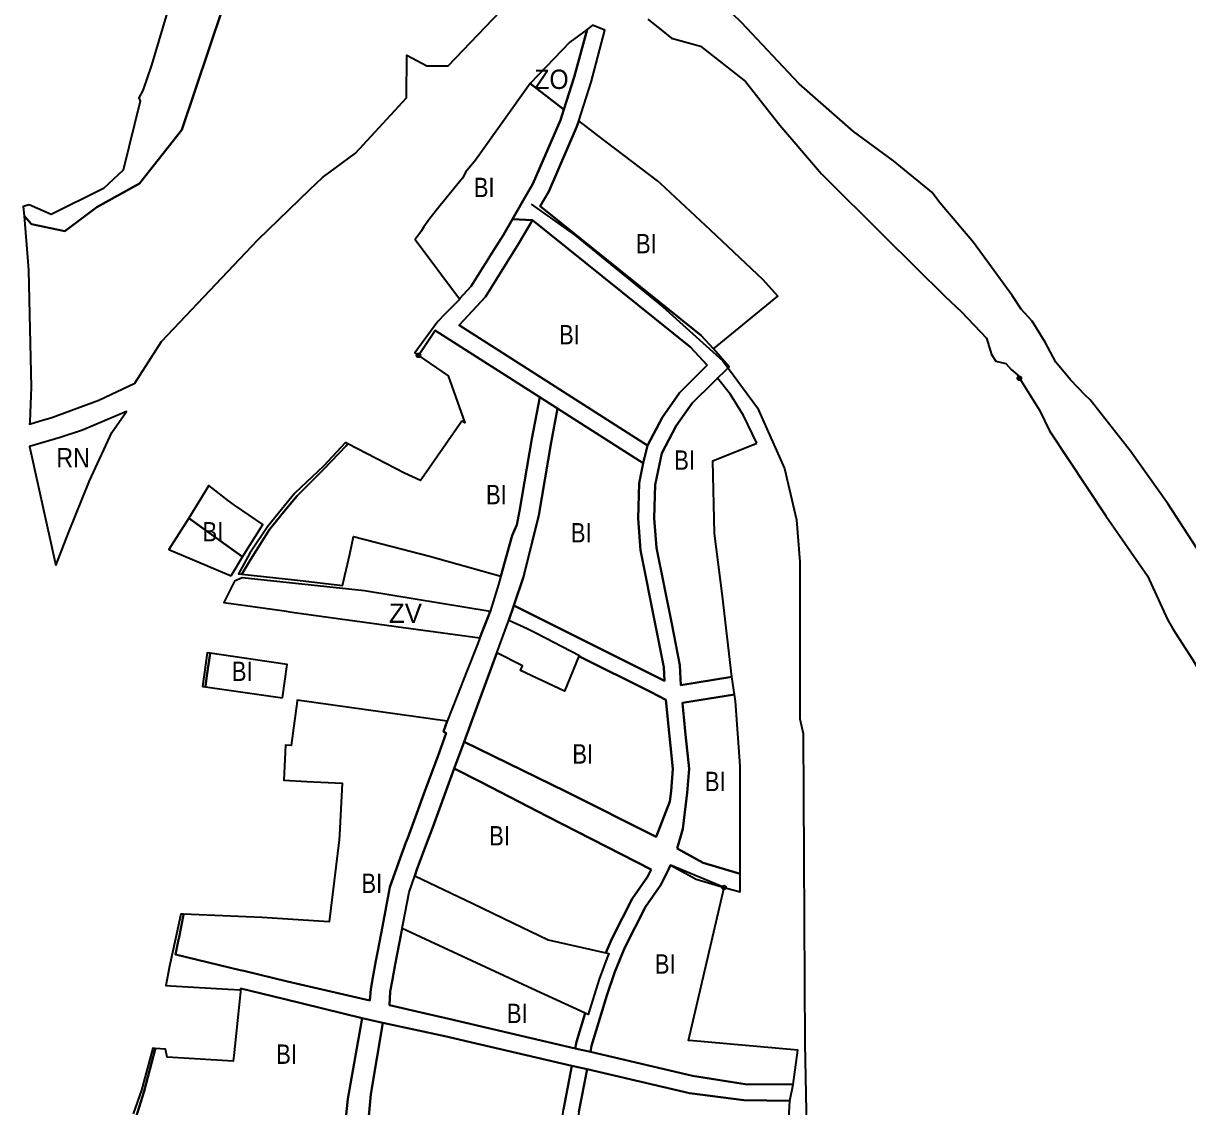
# Model space of a CAD drawing. Extents: x -650276 to -642489, y -1074311 to -1066658.
# Drawn here: x -645939 to -645218, y -1069899 to -1069228 of the extents above; entities that cross this region are included whole.
import ezdxf

# ---------------------------------------------------------------- set-up
doc = ezdxf.new("R2010")
doc.units = 0
doc.header["$LTSCALE"] = 4.8
doc.header["$PDMODE"] = 32
doc.header["$PDSIZE"] = 2.4
for name, color, linetype, lineweight in [('15', 7, 'Continuous', 35), ('2', 7, 'Continuous', 35), ('24', 7, 'Continuous', 35), ('40', 7, 'Continuous', 35), ('42', 7, 'Continuous', 35), ('48', 7, 'Continuous', 35), ('54', 7, 'Continuous', 35), ('7', 7, 'Continuous', 35)]:
    doc.layers.add(name, color=color, linetype=linetype, lineweight=lineweight)
doc.layers.add('62', color=7, linetype='Continuous')

msp = doc.modelspace()

# ---------------------------------------------------------------- linework, layer by layer
at = {"layer": '15'}
for p, q in [((-645552.336, -1069489.579), (-645555.072, -1069500.545)), ((-645638.203, -1069597.8), (-645635.153, -1069588.78))]:
    msp.add_line(p, q, dxfattribs=at)
for points in [[(-645589.844, -1069231.908), (-645597.738, -1069261.522), (-645604.114, -1069281.49)], [(-645594.94, -1069288.511), (-645587.298, -1069264.578), (-645578.713, -1069232.375), (-645586.39, -1069229.32), (-645589.844, -1069231.908)], [(-645604.114, -1069281.49), (-645606.256, -1069288.199), (-645623.307, -1069327.508), (-645628.492, -1069336.506), (-645635.995, -1069349.527), (-645623.694, -1069349.962)], [(-645618.766, -1069341.409), (-645613.576, -1069332.402), (-645596.062, -1069292.027), (-645594.94, -1069288.511)], [(-645511.585, -1069450.466), (-645501.878, -1069440.838), (-645511.464, -1069429.794), (-645519.097, -1069421.579), (-645618.766, -1069341.409)], [(-645669.039, -1069415.116), (-645652.804, -1069397.548), (-645632.191, -1069364.707), (-645623.694, -1069349.962), (-645635.995, -1069349.527)], [(-645635.995, -1069349.527), (-645641.511, -1069359.099), (-645647.304, -1069368.329), (-645659.41, -1069387.617)], [(-645623.694, -1069349.962), (-645525.761, -1069428.736), (-645515.509, -1069439.769)], [(-645659.41, -1069387.617), (-645661.477, -1069390.91), (-645668.722, -1069398.75)], [(-645668.722, -1069398.75), (-645668.61, -1069398.9), (-645678.06, -1069408.54)], [(-645678.06, -1069408.54), (-645682.28, -1069412.88), (-645696.45, -1069432.21), (-645694.21, -1069433.78)], [(-645619.119, -1069459.68), (-645608.04, -1069466.749), (-645555.072, -1069500.545), (-645552.336, -1069489.579), (-645669.039, -1069415.116)], [(-645694.21, -1069433.78), (-645683.883, -1069418.357), (-645619.119, -1069459.68)], [(-645515.509, -1069439.769), (-645532.534, -1069456.978), (-645543.158, -1069472.134), (-645552.336, -1069489.579), (-645555.072, -1069500.545)], [(-645531.753, -1069637.96), (-645532.36, -1069625.648), (-645537.354, -1069600.095), (-645546.74, -1069552.954), (-645548.207, -1069534.609), (-645547.654, -1069514.049), (-645543.548, -1069494.404), (-645534.584, -1069477.365), (-645524.812, -1069463.425), (-645511.585, -1069450.466)], [(-645739.3, -1069487.81), (-645753.05, -1069502.47), (-645770.66, -1069519.07), (-645780.85, -1069531.55), (-645787.64, -1069539.88), (-645798.53, -1069556.3), (-645805.66, -1069569.03), (-645803.513, -1069569.263)], [(-645752.715, -1069504.328), (-645738.986, -1069489.868), (-645737.897, -1069488.534), (-645739.3, -1069487.81)], [(-645555.072, -1069500.545), (-645557.65, -1069512.879), (-645558.241, -1069534.874), (-645556.685, -1069554.337), (-645547.188, -1069602.035), (-645542.336, -1069626.862), (-645541.922, -1069635.264), (-645635.153, -1069588.78), (-645638.203, -1069597.8)], [(-645803.513, -1069569.263), (-645798.102, -1069559.972), (-645786.388, -1069541.673), (-645779.376, -1069532.962), (-645778.754, -1069532.198), (-645769.369, -1069520.672), (-645768.995, -1069520.305), (-645752.715, -1069504.328)], [(-645638.203, -1069597.8), (-645626.95, -1069602.91), (-645621.56, -1069605.68), (-645594.58, -1069619.56), (-645594.818, -1069620.139), (-645550.62, -1069642.176), (-645541.064, -1069647.092)], [(-645826.151, -1069639.057), (-645826.133, -1069638.843), (-645825.295, -1069632.053), (-645823.13, -1069618.452), (-645823.082, -1069618.279), (-645824.95, -1069618.01), (-645827.94, -1069638.8)], [(-645530.797, -1069648.949), (-645498.61, -1069643.729), (-645500.137, -1069632.833), (-645531.753, -1069637.96)], [(-645827.94, -1069638.8), (-645826.149, -1069639.082), (-645826.151, -1069639.057)], [(-645541.064, -1069647.092), (-645538.744, -1069669.644), (-645538.15, -1069675.537)], [(-645533.953, -1069739.166), (-645530.534, -1069726.969), (-645527.824, -1069704.697), (-645526.643, -1069689.732), (-645528.772, -1069668.628), (-645530.797, -1069648.949)], [(-645538.15, -1069675.537), (-645536.707, -1069689.842), (-645537.8, -1069703.696), (-645538.579, -1069710.102), (-645546.93, -1069731.98), (-645602.91, -1069703.88), (-645665.961, -1069673.028), (-645671.999, -1069689.523), (-645655.45, -1069698.05), (-645614.28, -1069719.27), (-645550.184, -1069752.242)], [(-645539.126, -1069751.764), (-645538.096, -1069749.446), (-645522.277, -1069758.205), (-645504.976, -1069763.332), (-645495, -1069766), (-645495, -1069754.815), (-645518, -1069748), (-645533.953, -1069739.166)], [(-645587.785, -1069865.117), (-645587.052, -1069861.272), (-645577.497, -1069830.237), (-645572.56, -1069815.628), (-645566.341, -1069800.49), (-645553.635, -1069775.217), (-645544.108, -1069761.733), (-645539.126, -1069751.764)], [(-645550.184, -1069752.242), (-645552.437, -1069756.749), (-645561.956, -1069770.224), (-645573.652, -1069793.487)], [(-645573.652, -1069793.487), (-645575.153, -1069796.472), (-645578.134, -1069803.73)], [(-645578.134, -1069803.73), (-645576.34, -1069804.13), (-645577.52, -1069807.26), (-645582.31, -1069820.05), (-645589.23, -1069841.89), (-645590.964, -1069841.09)], [(-645726.131, -1069918.457), (-645723.668, -1069891.356), (-645716.277, -1069847.01), (-645729.006, -1069844.136), (-645738.039, -1069894.231), (-645742.967, -1069941.862)], [(-645590.964, -1069841.09), (-645596.458, -1069858.935), (-645597.216, -1069862.91), (-645587.785, -1069865.117)], [(-645869.262, -1069905.935), (-645863.95, -1069889.468), (-645857.289, -1069863.338), (-645857.204, -1069862.954), (-645858.78, -1069862.84), (-645865.78, -1069888.76), (-645870.89, -1069903.5)], [(-645594.866, -1069902.242), (-645589.84, -1069875.892), (-645599.271, -1069873.685), (-645604.424, -1069900.701)]]:
    msp.add_lwpolyline(points, dxfattribs=at)
msp.add_lwpolyline([(-645812.18, -1069826.3), (-645804.28, -1069826.76), (-645804.185, -1069825.84), (-645777.852, -1069832.241), (-645729.006, -1069844.136), (-645716.277, -1069847.01), (-645677.849, -1069855.3), (-645599.271, -1069873.685), (-645589.84, -1069875.892), (-645526.451, -1069890.745), (-645492.842, -1069895), (-645464.288, -1069895.362), (-645462.303, -1069885.376), (-645492, -1069885), (-645524.43, -1069879.921), (-645587.785, -1069865.117), (-645597.216, -1069862.91), (-645675.369, -1069844.625), (-645689.909, -1069841.272), (-645712.203, -1069836.131), (-645711.644, -1069827.736), (-645710.289, -1069820.217), (-645708.633, -1069811.027), (-645700.028, -1069766.286), (-645696.517, -1069756.039), (-645695.176, -1069752.125), (-645689.63, -1069737.38), (-645685.351, -1069726.002), (-645671.999, -1069689.523), (-645665.961, -1069673.028), (-645658.119, -1069651.601), (-645645.715, -1069618.085), (-645638.203, -1069597.8), (-645635.153, -1069588.78), (-645629.102, -1069570.857), (-645623.814, -1069549.548), (-645619.662, -1069532.642), (-645612.028, -1069487.724), (-645608.04, -1069466.749), (-645619.119, -1069459.68), (-645624.041, -1069485.561), (-645631.62, -1069530.161), (-645633.29, -1069538.7), (-645636.09, -1069545.31), (-645643.16, -1069570.6), (-645644.56, -1069575.61), (-645648.68, -1069589.06), (-645649.91, -1069592.39), (-645656.15, -1069608.71), (-645657.52, -1069612.2), (-645664.19, -1069629.24), (-645670.23, -1069644.67), (-645676.34, -1069660.28), (-645678.73, -1069666.78), (-645676.984, -1069667.634), (-645682.314, -1069682.197), (-645689.959, -1069703.082), (-645696.794, -1069721.756), (-645700.87, -1069732.593), (-645701.968, -1069735.514), (-645706.663, -1069747.998), (-645711.852, -1069763.14), (-645716.534, -1069787.483), (-645719.436, -1069802.573), (-645720.632, -1069808.792), (-645722.474, -1069819.017), (-645723.777, -1069826.243), (-645724.25, -1069833.353), (-645775.326, -1069821.576), (-645802.431, -1069814.987), (-645804.657, -1069814.455), (-645844.737, -1069804.875), (-645842.728, -1069795.578), (-645842.648, -1069795.17), (-645839.721, -1069780.247), (-645839.658, -1069779.835), (-645841.41, -1069779.76), (-645844.57, -1069795.07), (-645848.35, -1069812.09), (-645850.63, -1069824.09), (-645847.62, -1069824.26)], close=True, dxfattribs=at)
msp.add_point((-645694.21, -1069433.78), dxfattribs=at)
at = {"layer": '2'}
for p, q in [((-645526.643, -1069689.732), (-645527.824, -1069704.697)), ((-645701.968, -1069735.514), (-645700.87, -1069732.593))]:
    msp.add_line(p, q, dxfattribs=at)
for points in [[(-645628.492, -1069336.506), (-645623.307, -1069327.508), (-645606.256, -1069288.199), (-645604.114, -1069281.49), (-645625.11, -1069265.42), (-645658.9, -1069312.83), (-645664.89, -1069320.2), (-645667, -1069324.06), (-645680.8, -1069341.08), (-645687.22, -1069349), (-645690.81, -1069354.28), (-645692.38, -1069356.67), (-645696.19, -1069362.01), (-645668.722, -1069398.75)], [(-645594.94, -1069288.511), (-645596.062, -1069292.027), (-645613.576, -1069332.402), (-645618.766, -1069341.409), (-645519.097, -1069421.579)], [(-645519.097, -1069421.579), (-645511.464, -1069429.794), (-645471.738, -1069397.026), (-645480.72, -1069386.96), (-645513.41, -1069356.18), (-645544.26, -1069327.35), (-645546.19, -1069325.81), (-645583.13, -1069297.55), (-645594.94, -1069288.511)], [(-645647.304, -1069368.329), (-645641.511, -1069359.099), (-645635.995, -1069349.527), (-645628.492, -1069336.506)], [(-645623.694, -1069349.962), (-645632.191, -1069364.707), (-645652.804, -1069397.548), (-645669.039, -1069415.116), (-645552.336, -1069489.579)], [(-645515.509, -1069439.769), (-645525.761, -1069428.736), (-645623.694, -1069349.962)], [(-645668.722, -1069398.75), (-645661.477, -1069390.91), (-645659.41, -1069387.617), (-645647.304, -1069368.329)], [(-645552.336, -1069489.579), (-645543.158, -1069472.134), (-645532.534, -1069456.978), (-645515.509, -1069439.769)], [(-645511.585, -1069450.466), (-645524.812, -1069463.425), (-645534.584, -1069477.365), (-645543.548, -1069494.404), (-645547.654, -1069514.049), (-645548.207, -1069534.609)], [(-645484.783, -1069488.256), (-645493, -1069471), (-645501, -1069458), (-645508.994, -1069447.955), (-645511.585, -1069450.466)], [(-645608.04, -1069466.749), (-645612.028, -1069487.724), (-645619.662, -1069532.642), (-645623.814, -1069549.548), (-645629.102, -1069570.857), (-645635.153, -1069588.78), (-645541.922, -1069635.264)], [(-645541.922, -1069635.264), (-645542.336, -1069626.862), (-645547.188, -1069602.035), (-645556.685, -1069554.337), (-645558.241, -1069534.874), (-645557.65, -1069512.879), (-645555.072, -1069500.545), (-645608.04, -1069466.749)], [(-645500.137, -1069632.833), (-645506, -1069583), (-645511, -1069544), (-645512, -1069499), (-645484.783, -1069488.256)], [(-645548.207, -1069534.609), (-645546.74, -1069552.954), (-645537.354, -1069600.095)], [(-645537.354, -1069600.095), (-645532.36, -1069625.648), (-645531.753, -1069637.96), (-645500.137, -1069632.833)], [(-645823.082, -1069618.279), (-645823.13, -1069618.452), (-645825.295, -1069632.053), (-645826.133, -1069638.843), (-645826.151, -1069639.057), (-645778.45, -1069645.92)], [(-645778.45, -1069645.92), (-645775.46, -1069625.13), (-645823.082, -1069618.279)], [(-645645.715, -1069618.085), (-645658.119, -1069651.601), (-645665.961, -1069673.028), (-645602.91, -1069703.88), (-645546.93, -1069731.98), (-645538.579, -1069710.102)], [(-645538.15, -1069675.537), (-645538.744, -1069669.644), (-645541.064, -1069647.092), (-645550.62, -1069642.176), (-645594.818, -1069620.139), (-645603.7, -1069641.75), (-645630.93, -1069628.84), (-645629.78, -1069626.03), (-645645.715, -1069618.085)], [(-645495, -1069744), (-645495, -1069688), (-645498, -1069648), (-645498.61, -1069643.729), (-645530.793, -1069648.948), (-645530.757, -1069649.336)], [(-645700.87, -1069732.593), (-645696.794, -1069721.756), (-645689.959, -1069703.082), (-645682.314, -1069682.197), (-645676.984, -1069667.634), (-645678.73, -1069666.78), (-645676.34, -1069660.28), (-645726.57, -1069653.22), (-645769.264, -1069647.213), (-645769.36, -1069648), (-645773.02, -1069675.47), (-645776.45, -1069675.26), (-645777.62, -1069696.85), (-645763.24, -1069697.58), (-645741.43, -1069698.68), (-645743.01, -1069730.72), (-645743.36, -1069733.7), (-645749.48, -1069784.61), (-645791.2, -1069781.92), (-645839.658, -1069779.835)], [(-645530.757, -1069649.336), (-645528.772, -1069668.628), (-645526.643, -1069689.732)], [(-645538.579, -1069710.102), (-645537.8, -1069703.696), (-645536.707, -1069689.842), (-645538.15, -1069675.537)], [(-645550.184, -1069752.242), (-645614.28, -1069719.27), (-645655.45, -1069698.05), (-645671.999, -1069689.523), (-645685.351, -1069726.002), (-645689.63, -1069737.38), (-645695.176, -1069752.125), (-645696.517, -1069756.039), (-645660.57, -1069773.31)], [(-645527.824, -1069704.697), (-645530.534, -1069726.969), (-645533.953, -1069739.166)], [(-645716.534, -1069787.483), (-645711.852, -1069763.14), (-645706.663, -1069747.998), (-645701.968, -1069735.514)], [(-645533.953, -1069739.166), (-645518, -1069748), (-645495, -1069754.815), (-645495, -1069744)], [(-645574.28, -1069794.735), (-645573.652, -1069793.487), (-645561.956, -1069770.224), (-645552.437, -1069756.749), (-645550.184, -1069752.242)], [(-645504.976, -1069763.332), (-645538.096, -1069749.446), (-645539.126, -1069751.764), (-645544.108, -1069761.733)], [(-645577.497, -1069830.237), (-645587.052, -1069861.272), (-645587.785, -1069865.117), (-645524.43, -1069879.921), (-645492, -1069885), (-645462.303, -1069885.376), (-645459.312, -1069864.01), (-645526.374, -1069858.055), (-645527, -1069858), (-645504.976, -1069763.332)], [(-645544.108, -1069761.733), (-645553.635, -1069775.217), (-645566.341, -1069800.49), (-645572.56, -1069815.628), (-645577.497, -1069830.237)], [(-645660.57, -1069773.31), (-645635.79, -1069785.23), (-645613.84, -1069795.78), (-645578.134, -1069803.731), (-645576.185, -1069798.985)], [(-645839.658, -1069779.835), (-645839.721, -1069780.247), (-645842.648, -1069795.17)], [(-645722.474, -1069819.017), (-645720.632, -1069808.792), (-645719.436, -1069802.573), (-645716.534, -1069787.483)], [(-645590.964, -1069841.09), (-645623.75, -1069825.97), (-645704.355, -1069788.786), (-645708.633, -1069811.027), (-645710.289, -1069820.217), (-645711.644, -1069827.736), (-645712.203, -1069836.131)], [(-645842.648, -1069795.17), (-645842.728, -1069795.578), (-645844.737, -1069804.875), (-645804.657, -1069814.455)], [(-645576.185, -1069798.985), (-645575.153, -1069796.472), (-645574.28, -1069794.735)], [(-645804.657, -1069814.455), (-645802.431, -1069814.987), (-645775.326, -1069821.576), (-645724.25, -1069833.353)], [(-645724.25, -1069833.353), (-645723.777, -1069826.243), (-645722.474, -1069819.017)], [(-645712.203, -1069836.131), (-645689.909, -1069841.272), (-645675.369, -1069844.625), (-645597.216, -1069862.91)], [(-645597.216, -1069862.91), (-645596.458, -1069858.935), (-645590.964, -1069841.09)]]:
    msp.add_lwpolyline(points, dxfattribs=at)
for points in [[(-645778.754, -1069532.198), (-645779.376, -1069532.962), (-645786.388, -1069541.673), (-645798.102, -1069559.972), (-645803.513, -1069569.263), (-645769.04, -1069573), (-645741.14, -1069576.19), (-645736.8, -1069556.91), (-645734.5, -1069545.89), (-645687.29, -1069558.04), (-645643.16, -1069570.6), (-645636.09, -1069545.31), (-645633.29, -1069538.7), (-645631.62, -1069530.161), (-645624.041, -1069485.561), (-645619.119, -1069459.68), (-645683.883, -1069418.357), (-645694.21, -1069433.78), (-645675.91, -1069446.56), (-645665.58, -1069475.61), (-645667.31, -1069474.6), (-645690.84, -1069508.32), (-645692.87, -1069511.229), (-645702.82, -1069506.64), (-645737.897, -1069488.534), (-645738.986, -1069489.868), (-645752.715, -1069504.328), (-645768.995, -1069520.305), (-645769.369, -1069520.672)], [(-645803.07, -1069558.62), (-645790.62, -1069538.59), (-645799.07, -1069532.8), (-645808.1, -1069526.61), (-645811.75, -1069523.81), (-645824.05, -1069514.34), (-645836.44, -1069534.5)], [(-645810.08, -1069570.39), (-645803.07, -1069558.62), (-645836.44, -1069534.5), (-645848.78, -1069553.91)], [(-645806, -1069959), (-645768.424, -1069948.431), (-645742.967, -1069941.862), (-645738.039, -1069894.231), (-645729.006, -1069844.136), (-645777.852, -1069832.241), (-645804.185, -1069825.84), (-645808.28, -1069865.39), (-645808.84, -1069870.75), (-645849.79, -1069868.4), (-645850.92, -1069863.41), (-645857.204, -1069862.954), (-645857.289, -1069863.338), (-645863.95, -1069889.468), (-645869.262, -1069905.935), (-645874.219, -1069917.496), (-645880.431, -1069930.3), (-645833, -1069966)], [(-645606.07, -1069913.163), (-645604.424, -1069900.701), (-645599.271, -1069873.685), (-645677.849, -1069855.3), (-645716.277, -1069847.01), (-645723.668, -1069891.356), (-645726.131, -1069918.457), (-645726.542, -1069939.398), (-645699.889, -1069939.714), (-645670.325, -1069943.002), (-645625.979, -1069954.92), (-645614.072, -1069957.797)], [(-645589.84, -1069875.892), (-645594.866, -1069902.242), (-645598.491, -1069932.472), (-645601.753, -1069962.317), (-645547.4, -1069976.382), (-645490.814, -1069988.074), (-645469.701, -1069990.011), (-645469.701, -1069990.011), (-645464.288, -1069895.362), (-645492.842, -1069895), (-645526.451, -1069890.745)]]:
    msp.add_lwpolyline(points, close=True, dxfattribs=at)
msp.add_point((-645504.976, -1069763.332), dxfattribs=at)
at = {"layer": '24'}
for points in [[(-645202.56, -1069568.23), (-645230.1, -1069525.98), (-645253.4, -1069493.06), (-645278.31, -1069461.33), (-645281.4, -1069458.4), (-645290.5, -1069449.03), (-645299.61, -1069437.97), (-645306.16, -1069425.55), (-645314.14, -1069412.54), (-645321.1, -1069405.21), (-645326.59, -1069396.64), (-645350.63, -1069363.98), (-645371.12, -1069339.47), (-645376.38, -1069332.65), (-645400.07, -1069313.32), (-645424.8, -1069295.24), (-645458.45, -1069265.56), (-645494.13, -1069227.63), (-645515.89, -1069206.66), (-645534.25, -1069190.56), (-645543.43, -1069178.39)], [(-645552.2, -1069225.59), (-645537.44, -1069237.41), (-645519.59, -1069242.38), (-645491.63, -1069264.25), (-645470.44, -1069291.24), (-645444.62, -1069321.35), (-645405.7, -1069360.27), (-645368.13, -1069397.37), (-645358.04, -1069406.84), (-645342.49, -1069423.06), (-645339.31, -1069433.27), (-645336.66, -1069437.47), (-645330.57, -1069438.89), (-645327.2, -1069442.53), (-645323.36, -1069445.79), (-645322.13, -1069447.96)], [(-645322.13, -1069447.96), (-645309.62, -1069467.79), (-645303.57, -1069480.49), (-645268.57, -1069533.23), (-645242.75, -1069570.26), (-645230.42, -1069597.39), (-645227.27, -1069602.68), (-645225.7, -1069605.32), (-645214.76, -1069622.37), (-645198.41, -1069650.49), (-645185.17, -1069673.38), (-645179.12, -1069681.3), (-645170.3, -1069698.91), (-645158.43, -1069722.61), (-645153.44, -1069734.71), (-645140.27, -1069766.68), (-645123.84, -1069805.38), (-645108.74, -1069843.58), (-645094.42, -1069882.65), (-645083.31, -1069913.37), (-645071.53, -1069948.89), (-645063.96, -1069973.73), (-645063.23, -1069976.2), (-645062.57, -1069978.46)]]:
    msp.add_lwpolyline(points, dxfattribs=at)
msp.add_point((-645322.13, -1069447.96), dxfattribs=at)
at = {"layer": '40'}
msp.add_lwpolyline([(-645698.83, -1069602.85), (-645656.15, -1069608.71), (-645649.91, -1069592.39), (-645727.71, -1069579.61), (-645803.33, -1069571.62), (-645808.18, -1069573.7), (-645814.82, -1069586.81), (-645777.26, -1069592.07), (-645772.58, -1069592.73), (-645738.13, -1069597.46)], close=True, dxfattribs=at)
at = {"layer": '42'}
msp.add_lwpolyline([(-645604.114, -1069281.49), (-645597.738, -1069261.522), (-645589.844, -1069231.908), (-645600.55, -1069239.93), (-645625.11, -1069265.42)], close=True, dxfattribs=at)
at = {"layer": '48'}
msp.add_lwpolyline([(-645877.15, -1069319.06), (-645877.15, -1069319.06), (-645889.29, -1069330.52), (-645921.56, -1069346.6), (-645935.33, -1069340.64), (-645938.89, -1069341.56), (-645938.399, -1069347.452), (-645933.792, -1069352.53), (-645913.23, -1069356.892), (-645893.291, -1069341.938), (-645867.026, -1069327.317), (-645840.644, -1069294.052), (-645806.806, -1069193.112), (-645779.685, -1069122.296), (-645778.75, -1069108.98), (-645784.52, -1069075.66), (-645783.02, -1069061.84), (-645784.69, -1069060.74), (-645807.89, -1069094.51), (-645829.96, -1069154.65), (-645859.43, -1069254.08), (-645864.96, -1069269.78), (-645867.42, -1069274.21), (-645866.45, -1069276.32)], close=True, dxfattribs=at)
at = {"layer": '54'}
msp.add_lwpolyline([(-645624.473, -1069340.207), (-645597.606, -1069359.137), (-645542.894, -1069403.796), (-645505.738, -1069437.197), (-645484.202, -1069466.216), (-645467.655, -1069503.794), (-645460.072, -1069535.704), (-645458, -1069561.601), (-645458, -1069658.925), (-645456, -1069668), (-645455.002, -1069859.825), (-645453.95, -1069912.05), (-645458.804, -1069992.044), (-645455.073, -1070009.111)], dxfattribs=at)
at = {"layer": '7'}
msp.add_line((-645918.82, -1069563.81), (-645910.9, -1069543.64), dxfattribs=at)
for points in [[(-645806.806, -1069193.112), (-645840.644, -1069294.052), (-645867.026, -1069327.317), (-645893.291, -1069341.938), (-645913.23, -1069356.892), (-645933.792, -1069352.53), (-645938.399, -1069347.452), (-645936.046, -1069375.651), (-645935.58, -1069381.24), (-645933.97, -1069453.52), (-645934.8, -1069474.71), (-645935.05, -1069476.32), (-645928.99, -1069474.55), (-645921.13, -1069472.25), (-645892.03, -1069461.43), (-645869.91, -1069451.02), (-645853.28, -1069425.27), (-645838.17, -1069409.28), (-645819.62, -1069389.66), (-645793.63, -1069362.15), (-645761.411, -1069331.17), (-645753.58, -1069323.64), (-645733.1, -1069308.58), (-645701.62, -1069274.36), (-645701.33, -1069247.86), (-645689, -1069254.5), (-645675.82, -1069254.48), (-645643.34, -1069220.59)], [(-645910.9, -1069543.64), (-645897.92, -1069511.49), (-645884.01, -1069481.56), (-645875.02, -1069468.52), (-645902.19, -1069480.13), (-645916.13, -1069484.55), (-645934.97, -1069490.31), (-645918.82, -1069563.81)]]:
    msp.add_lwpolyline(points, dxfattribs=at)

# ---------------------------------------------------------------- texts
at = {"layer": '62'}
for s, width, p in [('ZO', 0.95, (-645622.428, -1069268.829)), ('BI', 0.85, (-645659.967, -1069335.79)), ('BI', 0.85, (-645559.537, -1069370.602)), ('BI', 0.85, (-645607.166, -1069426.988)), ('RN', 0.9, (-645918.459, -1069503.176)), ('BI', 0.85, (-645535.874, -1069504.638)), ('BI', 0.85, (-645652.376, -1069526.009)), ('BI', 0.85, (-645827.899, -1069548.998)), ('BI', 0.85, (-645599.874, -1069549.638)), ('BI', 0.85, (-645809.789, -1069635.433)), ('BI', 0.85, (-645598.928, -1069686.593)), ('BI', 0.85, (-645516.874, -1069703.638)), ('BI', 0.85, (-645650.447, -1069737.266)), ('BI', 0.85, (-645729.524, -1069766.68)), ('BI', 0.85, (-645547.874, -1069816.638)), ('BI', 0.85, (-645639.447, -1069847.266)), ('BI', 0.85, (-645782.319, -1069872.497))]:
    msp.add_text(s, height=12, dxfattribs=dict(at, width=width)).set_placement(p)
msp.add_text('ZV', height=12, dxfattribs=at).set_placement((-645712.51, -1069599.456))

doc.saveas('drawing.dxf')
